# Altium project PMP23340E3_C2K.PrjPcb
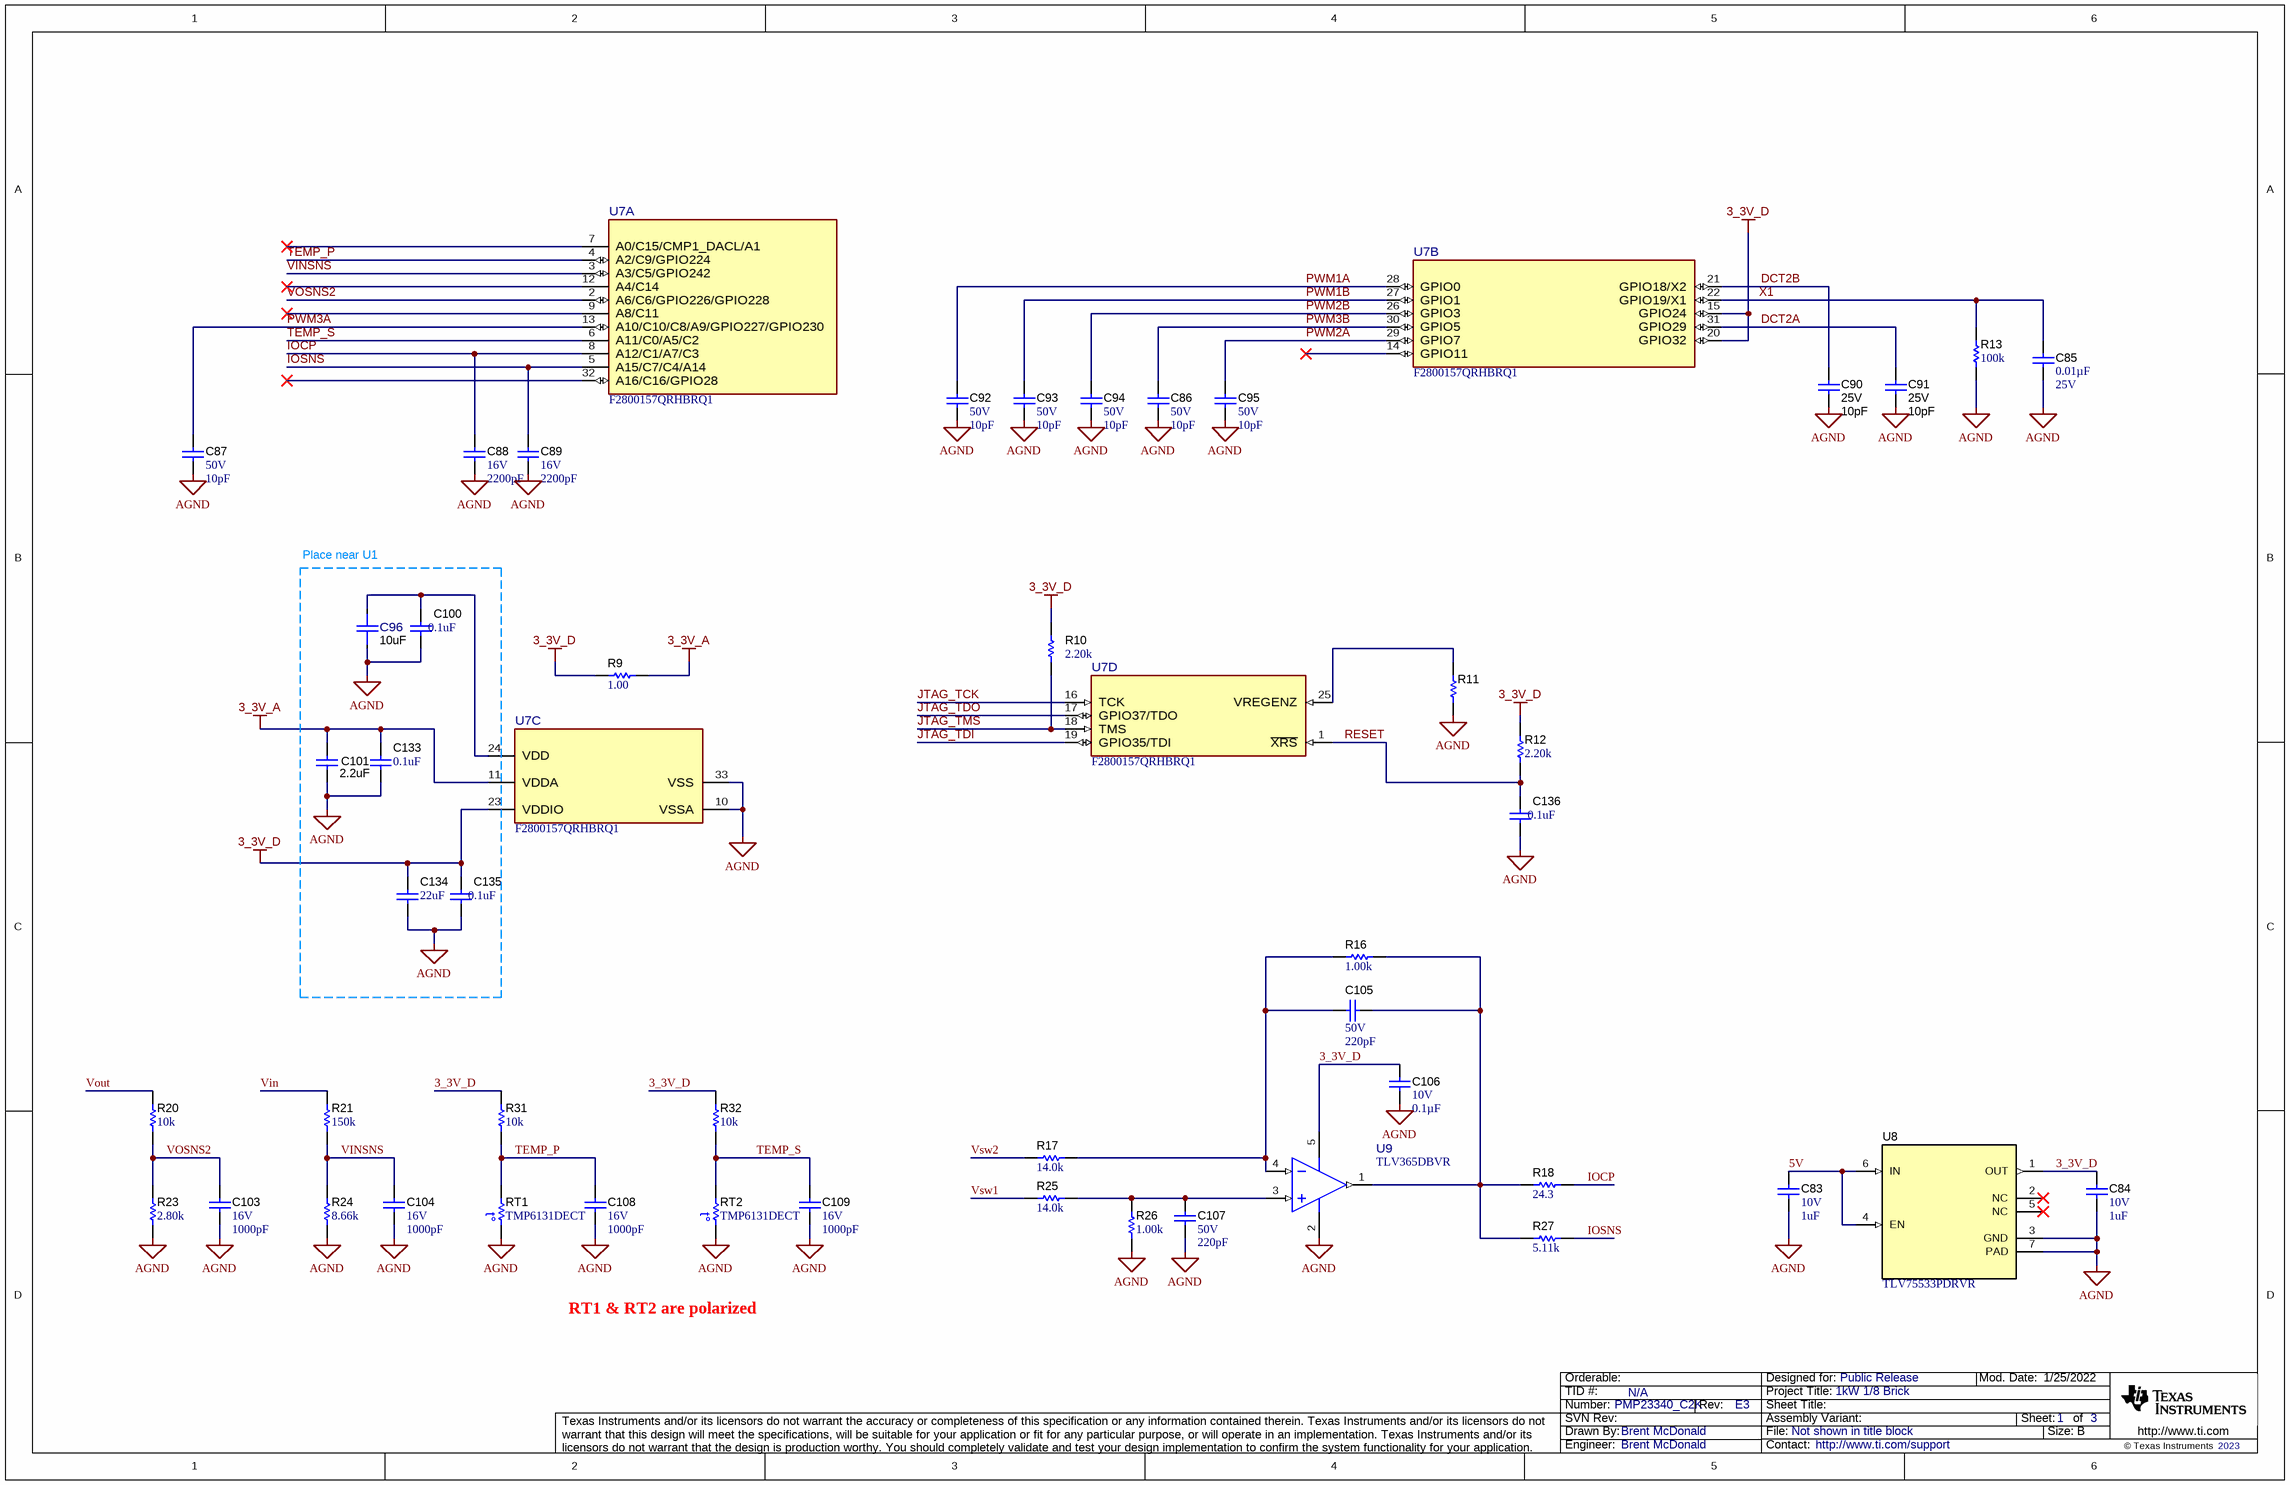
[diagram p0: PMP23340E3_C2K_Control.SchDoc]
CopyrightYear: 2023; DrawnBy: Brent McDonald; PCB_Layout: Brent McDonald; PCB_Rev: E3; PRJ_Customer: Public Release; PRJ_Engineer: Brent McDonald; PRJ_Number: PMP23340_C2K; PRJ_Title: 1kW 1/8 Brick; SCH_Rev: E3; TechSupport: http://www.ti.com/support; TID: N/A
3 sheets, 242 parts. Net scope: global (net labels, ports and power ports of the same name join across sheets).
Board file: PMP23340E3_C2K.PcbDoc
Sheets:
  PMP23340E3_C2K_Control.SchDoc
  PMP23340E3_C2K_Power_Stage.SchDoc
  PMP23340E3_C2K_Hardware.SchDoc

## Sheet PMP23340E3_C2K_Control.SchDoc
size 431 x 279 mm; Date: Not shown in title block; ApprovedBy: Not shown in title block; CheckedBy: Not shown in title block; Author: Not shown in title block; CompanyName: Not shown in title block; Engineer: Not shown in title block; Organization: Not shown in title block; Address1: Not shown in title block; Address2: Not shown in title block; Address3: Not shown in title block; Address4: Not shown in title block; DocumentNumber: 1; Revision: Use project parameter SCH_Rev; SheetNumber: 1; SheetTotal: 3; PageSetup: Record=PageOptions¦CenterHorizontal=True¦CenterVertical=True¦PrintScale=1.00¦XCorrection=1.00¦YCorrection=1.00¦PrintKind=0¦BorderSize=5000000¦LeftOffset=0¦BottomOffset=0¦Orientation=2¦PaperLength=1000¦PaperWidth=1000¦Scale=100¦PaperSource=15¦PrintQuality=600¦MediaType=1¦DitherType=10¦PaperKind=Letter¦PrintScaleMode=1

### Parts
C83  VDC_V: 10V  ValueDisplayed: 1uF  [0201]  (hidden comment: GRM033R61A105ME15D)
C84  VDC_V: 10V  ValueDisplayed: 1uF  [0201]  (hidden comment: GRM033R61A105ME15D)
C85  ValueDisplayed: 0.01µF  VDC_V: 25V  [0201_033]  (hidden comment: GRM033R61E103KA12D)
C86  VDC_V: 50V  ValueDisplayed: 10pF  [0201_033]  (hidden comment: GRM0335C1H100JA01D)
C87  VDC_V: 50V  ValueDisplayed: 10pF  [0201_033]  (hidden comment: GRM0335C1H100JA01D)
C88  VDC_V: 16V  ValueDisplayed: 2200pF  [0201]  (hidden comment: GRM033R71C222KA88D)
C89  VDC_V: 16V  ValueDisplayed: 2200pF  [0201]  (hidden comment: GRM033R71C222KA88D)
C90  VDC_V: 25V  ValueDisplayed: 10pF  [0201]  (hidden comment: GJM0335C1E100JB01D)
C91  VDC_V: 25V  ValueDisplayed: 10pF  [0201]  (hidden comment: GJM0335C1E100JB01D)
C92  VDC_V: 50V  ValueDisplayed: 10pF  [0201_033]  (hidden comment: GRM0335C1H100JA01D)
C93  VDC_V: 50V  ValueDisplayed: 10pF  [0201_033]  (hidden comment: GRM0335C1H100JA01D)
C94  VDC_V: 50V  ValueDisplayed: 10pF  [0201_033]  (hidden comment: GRM0335C1H100JA01D)
C95  VDC_V: 50V  ValueDisplayed: 10pF  [0201_033]  (hidden comment: GRM0335C1H100JA01D)
C96  ValueDisplayed: 10uF  [FP-CC0603KRX5R6BB106_0603-MFG]  (hidden comment: CC0603KRX5R6BB106)
C100  ValueDisplayed: 0.1uF  [0201]  (hidden comment: GRM033Z71C104KE14D)
C101  ValueDisplayed: 2.2uF  [0603]  (hidden comment: GRM188R61A225KE34D)
C103  VDC_V: 16V  ValueDisplayed: 1000pF  [0201]  (hidden comment: GRM033R71C102KA01D)
C104  VDC_V: 16V  ValueDisplayed: 1000pF  [0201]  (hidden comment: GRM033R71C102KA01D)
C105  VDC_V: 50V  ValueDisplayed: 220pF  [0201_033]  (hidden comment: CGA1A2X7R1H221K030BA)
C106  VDC_V: 10V  ValueDisplayed: 0.1µF  [0201_033L]  (hidden comment: ATC530Z104KT10T)
C107  VDC_V: 50V  ValueDisplayed: 220pF  [0201_033]  (hidden comment: CGA1A2X7R1H221K030BA)
C108  VDC_V: 16V  ValueDisplayed: 1000pF  [0201]  (hidden comment: GRM033R71C102KA01D)
C109  VDC_V: 16V  ValueDisplayed: 1000pF  [0201]  (hidden comment: GRM033R71C102KA01D)
C133  ValueDisplayed: 0.1uF  [0201]  (hidden comment: GRM033Z71C104KE14D)
C134  ValueDisplayed: 22uF  [0603]  (hidden comment: GRM187R61A226ME15D)
C135  ValueDisplayed: 0.1uF  [0201]  (hidden comment: GRM033Z71C104KE14D)
C136  ValueDisplayed: 0.1uF  [0201]  (hidden comment: GRM033Z71C104KE14D)
R9  ValueDisplayed: 1.00  [0201]  (hidden comment: RC0201FR-071RL)
R10  ValueDisplayed: 2.20k  [0201]  (hidden comment: CRCW02012K20FKED)
R11  RC0201JR-070RL  [FP-RC0201JR-070RL_0201 (0603 Metric)-IPC_C]  (value not drawn)
R12  ValueDisplayed: 2.20k  [0201]  (hidden comment: CRCW02012K20FKED)
R13  ValueDisplayed: 100k  [0402]  (hidden comment: RG1005P-104-B-T5)
R16  ValueDisplayed: 1.00k  [0201]  (hidden comment: RC0201FS-7D1KL)
R17  ValueDisplayed: 14.0k  [0402]  (hidden comment: RC0402FR-0714KL)
R18  ValueDisplayed: 24.3  [0201]  (hidden comment: RC0201FS-7D24R3L)
R20  ValueDisplayed: 10k  [0201]  (hidden comment: RC0201JR-7D10KL)
R21  ValueDisplayed: 150k  [0402]  (hidden comment: ERJ-2RKF1503X)
R23  ValueDisplayed: 2.80k  [0201]  (hidden comment: RC0201FR-072K8L)
R24  ValueDisplayed: 8.66k  [0201]  (hidden comment: RC0201FR-078K66L)
R25  ValueDisplayed: 14.0k  [0402]  (hidden comment: RC0402FR-0714KL)
R26  ValueDisplayed: 1.00k  [0201]  (hidden comment: RC0201FS-7D1KL)
R27  ValueDisplayed: 5.11k  [0201]  (hidden comment: RC0201FR-075K11L)
R31  ValueDisplayed: 10k  [0201]  (hidden comment: RC0201JS-7D10KL)
R32  ValueDisplayed: 10k  [0201]  (hidden comment: RC0201JS-7D10KL)
RT1  TMP6131DECT  [DEC0002A]
RT2  TMP6131DECT  [DEC0002A]
U7  F2800157QRHBRQ1  [RHB0032E-MFG]  (parts A,B,C,D of 4)
U8  TLV75533PDRVR  [DRV0006A]
U9  TLV365DBVR  [DBV0005A-MFG]

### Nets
3_3V_A: C101.1 C133.1 R9.2 U7.11(VDDA)
3_3V_D: C84.1 C106.1 C134.1 C135.1 R9.1 R10.2 R12.2 R31.2 R32.2 U7.15(GPIO24) U7.20(GPIO32) U7.23(VDDIO) U8.1(OUT) U9.5(V+)
AGND: C83.2 C84.2 C85.2 C86.2 C87.2 C88.1 C89.1 C90.2 C91.2 C92.2 C93.2 C94.2 C95.2 C96.1 C100.2 C101.2 C103.1 C104.1 C106.2 C107.1 C108.1 C109.1 C133.2 C134.2 C135.2 C136.2 R11.1 R13.2 R23.1 R24.1 R26.1 RT1.2 RT2.2 U7.10(VSSA) U7.33(VSS) U8.3(GND) U8.7(PAD) U9.2(V-)
5V: C83.1 U8.4(EN) U8.6(IN)
DCT2A: C91.1 U7.31(GPIO29)
DCT2B: C90.1 U7.21(GPIO18/X2)
IOCP: C88.2 R18.2 U7.8(A12/C1/A7/C3)
IOSNS: C89.2 R27.2 U7.5(A15/C7/C4/A14)
JTAG_TCK: U7.16(TCK)
JTAG_TDI: U7.19(GPIO35/TDI)
JTAG_TDO: U7.17(GPIO37/TDO)
JTAG_TMS: R10.1 U7.18(TMS)
PWM1A: C92.1 U7.28(GPIO0)
PWM1B: C93.1 U7.27(GPIO1)
PWM2A: C95.1 U7.29(GPIO7)
PWM2B: C94.1 U7.26(GPIO3)
PWM3A: C87.1 U7.13(A10/C10/C8/A9/GPIO227/GPIO230)
PWM3B: C86.1 U7.30(GPIO5)
RESET: C136.1 R12.1 U7.1(~{XRS})
TEMP_P: C108.2 R31.1 RT1.1 U7.4(A2/C9/GPIO224)
TEMP_S: C109.2 R32.1 RT2.1 U7.6(A11/C0/A5/C2)
Vin: R21.2
VINSNS: C104.2 R21.1 R24.2 U7.3(A3/C5/GPIO242)
VOSNS2: C103.2 R20.1 R23.2 U7.2(A6/C6/GPIO226/GPIO228)
Vout: R20.2
Vsw1: R25.1
Vsw2: R17.1
X1: C85.1 R13.1 U7.22(GPIO19/X1)
NetC96_2: C96.2 C100.1 U7.24(VDD)
NetC105_1: C105.1 R16.1 R18.1 R27.1 U9.1(VOUT)
NetC105_2: C105.2 R16.2 R17.2 U9.4(-IN)
NetC107_2: C107.2 R25.2 R26.2 U9.3(+IN)
NetR11_2: R11.2 U7.25(VREGENZ)

Not connected (* = marked no-connect by the designer): U7 7(A0/C15/CMP1_DACL/A1)* 9(A8/C11)* 12(A4/C14)* 14(GPIO11)* 32(A16/C16/GPIO28)*; U8 2(NC)* 5(NC)*

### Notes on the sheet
- Place near U1
- RT1 & RT2 are polarized

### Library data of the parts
C83 C84 = CMP-0064909-1: CAP, CERM, 1 uF, 10 V,+/- 20%, X5R, 0201; Manufacturer: MuRata; TaMin_C: -55°C; Polarized: N; SizeAreaWB_mm2: 2.08; Value1: Unknown; U/M: EA; Value: 1uF; TaMax_C: 85°C; SizeZ_mm: 0.26; SizeX_mm: 0.6; SizeY_mm: 0.3; SizeArea_mm2: 0.18; Cap_F: 1µF; AEC Category: Q200
C85 = CMP-0086060-1: CAP, CERM, 0.01 µF, 25 V,+/- 10%, X5R, 0201; Manufacturer: MuRata; SizeY_mm: 0.3; SizeZ_mm: 0.33; SizeAreaWB_mm2: 2.08; U/M: EA; AEC Category: Q200; SizeX_mm: 0.6; TaMin_C: -55°C; Polarized: N; TaMax_C: 85°C; Value: 0.01uF; Cap_F: 10nF; SizeArea_mm2: 0.18; Cap_Case: 0201
C86 C87 C92-C95 = CMP-0086057-1: CAP, CERM, 10 pF, 50 V,+/- 5%, C0G/NP0, 0201; Manufacturer: MuRata; SizeArea_mm2: 0.18; AEC Category: Q200; SizeX_mm: 0.6; SizeZ_mm: 0.33; Value: 10pF; TaMin_C: -55°C; SizeAreaWB_mm2: 2.08; U/M: EA; AEC Qualified: N; Cap_Case: 0201; SizeY_mm: 0.3; TaMax_C: 125°C
C88 C89 = CMP-0009752-1: CAP, CERM, 2200 pF, 16 V, +/- 10%, X7R, 0201; Manufacturer: MuRata; TaMin_C: -55°C; Polarized: N; SizeAreaWB_mm2: 2.08; Value1: Unknown; U/M: EA; Value: 2200pF; TaMax_C: 125°C; SizeZ_mm: 0.26; SizeX_mm: 0.6; SizeY_mm: 0.3; SizeArea_mm2: 0.18; Cap_F: 2.2nF; AEC Category: Q200
C90 C91 = CMP-0009661-3: CAP, CERM, 10 pF, 25 V, +/- 5%, C0G/NP0, 0201; Manufacturer: MuRata; TaMin_C: -55°C; Polarized: N; SizeAreaWB_mm2: 2.08; Value1: Unknown; U/M: EA; Value: 10pF; TaMax_C: 125°C; SizeZ_mm: 0.26; SizeX_mm: 0.6; SizeY_mm: 0.3; SizeArea_mm2: 0.18; AEC Category: Q200
C96 = CMP-0092309-1: Cap Ceramic 10uF 10V X5R 10% SMD 0603 85C Paper T/R; Manufacturer: YAGEO; Cap_F: 10µF; TempCo: 15%; Category 7542B8484461Ae85: Passive Components; Category 4C11811B7D3097D6: Single Components; SizeZ_mm: 1mm; Category F8883582C9A8234F: Capacitors; AEC Qualified: No; Value: 10µF; Category 85Ce48C4B2B95E09: Uncategorized
C100 C133 C135 C136 = CMP-0064970-1: CAP, CERM, 0.1 uF, 16 V,+/- 10%, X7R, 0201; Manufacturer: MuRata; AEC Qualified: N; Value: 0.1uF; SizeZ_mm: 0.26; VDC_V: 16V; Cap_F: 100nF; TaMin_C: -55°C; SizeAreaWB_mm2: 2.08; Value1: Unknown; U/M: EA; TaMax_C: 125°C; SizeX_mm: 0.6; SizeY_mm: 0.3; SizeArea_mm2: 0.18; AEC Category: Q200
C101 = CMP-0007323-5: CAP, CERM, 2.2 uF, 10 V, +/- 10%, X5R, 0603; Manufacturer: MuRata; Polarized: N; Value: 2.2uF; U/M: EA; Cap_F: 2.2µF; Value1: Unknown; VDC_V: 10V; TaMin_C: -55°C; TaMax_C: 85°C; SizeArea_mm2: 1.28; SizeAreaWB_mm2: 4.68; SizeX_mm: 1.6; SizeY_mm: 0.8; SizeZ_mm: 1; AEC Category: Q200
C103 C104 C108 C109 = CMP-0009745-1: CAP, CERM, 1000 pF, 16 V, +/- 10%, X7R, 0201; Manufacturer: MuRata; TaMin_C: -55°C; Polarized: N; SizeAreaWB_mm2: 2.08; Value1: Unknown; U/M: EA; Value: 1000pF; TaMax_C: 125°C; SizeZ_mm: 0.26; SizeX_mm: 0.6; SizeY_mm: 0.3; SizeArea_mm2: 0.18; Cap_F: 1nF; AEC Category: Q200
C105 C107 = CMP-0009652-3: CAP, CERM, 220 pF, 50 V, +/- 10%, X7R, AEC-Q200 Grade 1, 0201; Manufacturer: TDK; TaMin_C: -55°C; ESR_ohm: 11.6275; Polarized: N; SizeAreaWB_mm2: 2.08; Value1: 11.6275 ohm; U/M: EA; Value: 220pF; TaMax_C: 125°C; SizeZ_mm: 0.33; SizeX_mm: 0.6; SizeY_mm: 0.3; SizeArea_mm2: 0.18; AEC Qualified: Y; IRMS_A: 200.785mA; AEC Grade: 1; AEC Category: Q200
C106 = CMP-0076713-1: CAP, CERM, 0.1 µF, 10 V,+/- 10%, X5R, 0201; Manufacturer: AT Ceramics; Cap_F: 100nF; SizeAreaWB_mm2: 2.08; SizeArea_mm2: 0.18; AEC Qualified: N; AEC Category: Q200; Value: 0.1uF; TaMax_C: 85°C; SizeZ_mm: 0.33; TaMin_C: -55°C; SizeY_mm: 0.3; U/M: EA; SizeX_mm: 0.6; Cap_Case: 0201
C134 = CMP-0007158-5: CAP, CERM, 22 uF, 10 V, +/- 20%, X5R, 0603; Manufacturer: MuRata; Cap_F: 22µF; SizeZ_mm: 1; VDC_V: 10V; AEC Qualified: N; Value: 22uF; TaMin_C: -55°C; SizeAreaWB_mm2: 4.68; Value1: Unknown; U/M: EA; TaMax_C: 85°C; SizeX_mm: 1.6; SizeY_mm: 0.8; SizeArea_mm2: 1.28; AEC Category: Q200
R9 = CMP-0027472-1: RES, 1.00, 1%, 0.05 W, 0201; Manufacturer: Yageo America; Power_W: 50mW; TempCo: 350 ppm/C; Value_Code: 1R00; U/M: EA; Value: 1.00; EIA_Code: E96; Res_ohm: 1; SizeX_mm: 0.6; SizeY_mm: 0.3; SizeZ_mm: 0.26; Value2: 0.05W; SizeArea_mm2: 0.18; AEC Qualified: N; VDC_V: 25V; AEC Category: Q200
R10 R12 = CMP-0027272-3: RES, 2.20 k, 1%, 0.05 W, 0201; Manufacturer: Vishay-Dale; Value: 2.20k; Res_ohm: 2.2k; Value_Code: 2k20; Power_W: 50mW; Value2: 0.05W; VDC_V: 30V; TempCo: 100 ppm/C; AEC Category: Q200; AEC Qualified: N; SizeArea_mm2: 0.18; SizeX_mm: 0.6; SizeY_mm: 0.3; SizeZ_mm: 0.26
R11 = CMP-0086442-2: RES SMD 0 OHM JUMPER 1/20W 0201; Manufacturer: Yageo; Res_ohm: 0; Tolerance_%: 5%; Power_W: 50mW; VDC_V: 25V; TempCo: 200ppm/°C; AEC Qualified: No; SizeZ_mm: 0.26mm
R13 = CMP-0026815-1: RES, 100 k, 0.1%, 0.063 W, 0402; Manufacturer: Susumu Co Ltd; Power_W: 63mW; TempCo: 25 ppm/C; U/M: EA; Value: 100k; EIA_Code: E192; SizeX_mm: 1; SizeY_mm: 0.5; SizeZ_mm: 0.6; Value2: 0.063W; AEC Category: Q200
R16 R26 = CMP-0028084-1: RES, 1.00 k, 1%, 0.05 W, 0201; Manufacturer: Yageo America; Power_W: 50mW; TempCo: 200 ppm/C; Value_Code: 1k00; U/M: EA; Value: 1.00k; EIA_Code: E96; Res_ohm: 1k; SizeX_mm: 0.6; SizeY_mm: 0.3; SizeZ_mm: 0.26; Value2: 0.05W; SizeArea_mm2: 0.18; AEC Qualified: N; VDC_V: 25V; AEC Category: Q200
R17 R25 = CMP-0860046-1: RES, 14.0 k, 1%, 0.0625 W, 0402; Manufacturer: Yageo; Power_W: 62.5mW; TempCo: 100 ppm/C; Value_Code: 14k0; Value: 14.0k; EIA_Code: E96; Res_ohm: 14k; SizeX_mm: 1; SizeY_mm: 0.5; SizeZ_mm: 0.6; AEC Qualified: N; VDC_V: 50V; AEC Category: Q200; SizeAreaWB_mm2: 3
R18 = CMP-0028092-1: RES, 24.3, 1%, 0.05 W, 0201; Manufacturer: Yageo America; Power_W: 50mW; TempCo: 200 ppm/C; Value_Code: 24R3; U/M: EA; Value: 24.3; EIA_Code: E96; SizeX_mm: 0.6; SizeY_mm: 0.3; SizeZ_mm: 0.26; Value2: 0.05W; SizeArea_mm2: 0.18; AEC Qualified: N; VDC_V: 25V; AEC Category: Q200
R20 = CMP-0027186-1: RES, 10 k, 5%, 0.05 W, 0201; Manufacturer: Yageo America; Power_W: 50mW; TempCo: 200 ppm/C; Value_Code: 10k0; U/M: EA; Value: 10k; EIA_Code: E24; SizeX_mm: 0.6; SizeY_mm: 0.3; SizeZ_mm: 0.26; Value2: 0.05W; SizeArea_mm2: 0.18; AEC Qualified: N; VDC_V: 25V; AEC Category: Q200
R21 = CMP-0026669-1: RES, 150 k, 1%, 0.1 W, AEC-Q200 Grade 0, 0402; Manufacturer: Panasonic; Power_W: 100mW; TempCo: 100 ppm/C; U/M: EA; Value: 150k; EIA_Code: E96; SizeX_mm: 1; SizeY_mm: 0.5; SizeZ_mm: 0.6; Value2: 0.1W; AEC Qualified: Y; VDC_V: 50V; AEC Grade: 0; AEC Category: Q200
R23 = CMP-0027570-1: RES, 2.80 k, 1%, 0.05 W, 0201; Manufacturer: Yageo America; Power_W: 50mW; TempCo: 200 ppm/C; Value_Code: 2k80; U/M: EA; Value: 2.80k; EIA_Code: E96; Res_ohm: 2.8k; SizeX_mm: 0.6; SizeY_mm: 0.3; SizeZ_mm: 0.26; Value2: 0.05W; SizeArea_mm2: 0.18; AEC Qualified: N; VDC_V: 25V; AEC Category: Q200
R24 = CMP-0027911-1: RES, 8.66 k, 1%, 0.05 W, 0201; Manufacturer: Yageo America; Power_W: 50mW; TempCo: 200 ppm/C; Value_Code: 8k66; U/M: EA; Value: 8.66k; EIA_Code: E96; SizeX_mm: 0.6; SizeY_mm: 0.3; SizeZ_mm: 0.26; Value2: 0.05W; SizeArea_mm2: 0.18; AEC Qualified: N; VDC_V: 25V; AEC Category: Q200
R27 = CMP-0027788-1: RES, 5.11 k, 1%, 0.05 W, 0201; Manufacturer: Yageo America; Power_W: 50mW; TempCo: 200 ppm/C; Value_Code: 5k11; U/M: EA; Value: 5.11k; EIA_Code: E96; SizeX_mm: 0.6; SizeY_mm: 0.3; SizeZ_mm: 0.26; Value2: 0.05W; SizeArea_mm2: 0.18; AEC Qualified: N; VDC_V: 25V; AEC Category: Q200
R31 R32 = CMP-0027260-1: RES, 10 k, 5%, 0.05 W, 0201; Manufacturer: Yageo America; Power_W: 50mW; TempCo: 200 ppm/C; Value_Code: 10k0; U/M: EA; Value: 10k; EIA_Code: E24; SizeX_mm: 0.6; SizeY_mm: 0.3; SizeZ_mm: 0.26; Value2: 0.05W; SizeArea_mm2: 0.18; AEC Qualified: N; VDC_V: 25V; AEC Category: Q200
RT1 RT2 = CMP-0084565-1: Thermistor, DEC0002A (X1SON-2); Alternate Manufacturer: Texas Instruments; Alternate PartNumber: TMP6131DECR; SizeZ_mm: 0.5; CompType: IC; AEC Category: Q200; SizeArea_mm2: 0.6; AEC Qualified: N; SizeX_mm: 1; SizeAreaWB_mm2: 3.2
U7 = CMP-0097759-1: Real-Time Microcontrollers VQFN32 TMS320C28x 32bit 120MHz; Manufacturer: Texas Instruments; AEC Grade: Grade 1; Max Supply Voltage: 3.63V; Min Supply Voltage: 1.14V; Number Of A/D Converters: 2; Number Of I/Os: 18; Number Of Timers/Counters: 3; SizeZ_mm: 1mm; Standoff Height: 0mm; Memory Type: FLASH; Ram Size: 36KBytes; TJmax_C: +140°C; Data Bus Width: 32bits; Interface: I2C,SPI,UART,CAN,LIN,SCI,Other; Memory Size: 256KBytes; Number Of Adc Channels: 11; Number Of Spi Channels: 1; AEC Qualified: Yes; Number Of Uart Channels: 4; Number Of Pwm Channels: 14; TaMax_C: +125°C; TaMin_C: -40°C
U8 = CMP-0013427-7: 500mA LDO, DRV0006A (WSON-6); Manufacturer: Texas Instruments; SizeX_mm: 2; CompType: IC; SizeZ_mm: 0.8; SizeArea_mm2: 4; SizeAreaWB_mm2: 9; U/M: EA
U9 = CMP-0032028-2: CMOS Amplifier 1 Circuit Rail-to-Rail SOT-23-5; Manufacturer: Texas Instruments; Number Of Channels: 1; Gain Bandwidth: 50MHz; SizeZ_mm: 1.45mm; AEC Qualified: No; Input Bias Current: 0.000005uA; Input Offset Voltage: 0.4mV; Max Supply Voltage: 5.5V; Min Supply Voltage: 2.2V; Nominal Supply Current: 4.6mA; Output Current Per Channel: 85mA; Response Time: 0.2us; Standoff Height: 0mm; TaMax_C: +125°C; TaMin_C: -40°C; TJmax_C: +150°C; Voltage Gain: 120dB; AEC Category: Q200; CompType: IC

## Sheet PMP23340E3_C2K_Power_Stage.SchDoc
size 431 x 279 mm; Date: Not shown in title block; ApprovedBy: Not shown in title block; CheckedBy: Not shown in title block; Author: Not shown in title block; CompanyName: Not shown in title block; Engineer: Not shown in title block; Organization: Not shown in title block; Address1: Not shown in title block; Address2: Not shown in title block; Address3: Not shown in title block; Address4: Not shown in title block; DocumentNumber: 2; Revision: Use project parameter SCH_Rev; SheetNumber: 2; SheetTotal: 3; PageSetup: Record=PageOptions¦CenterHorizontal=True¦CenterVertical=True¦PrintScale=1.00¦XCorrection=1.00¦YCorrection=1.00¦PrintKind=0¦BorderSize=5000000¦LeftOffset=0¦BottomOffset=0¦Orientation=2¦PaperLength=1000¦PaperWidth=1000¦Scale=100¦PaperSource=15¦PrintQuality=600¦MediaType=1¦DitherType=10¦PaperKind=Letter¦PrintScaleMode=1
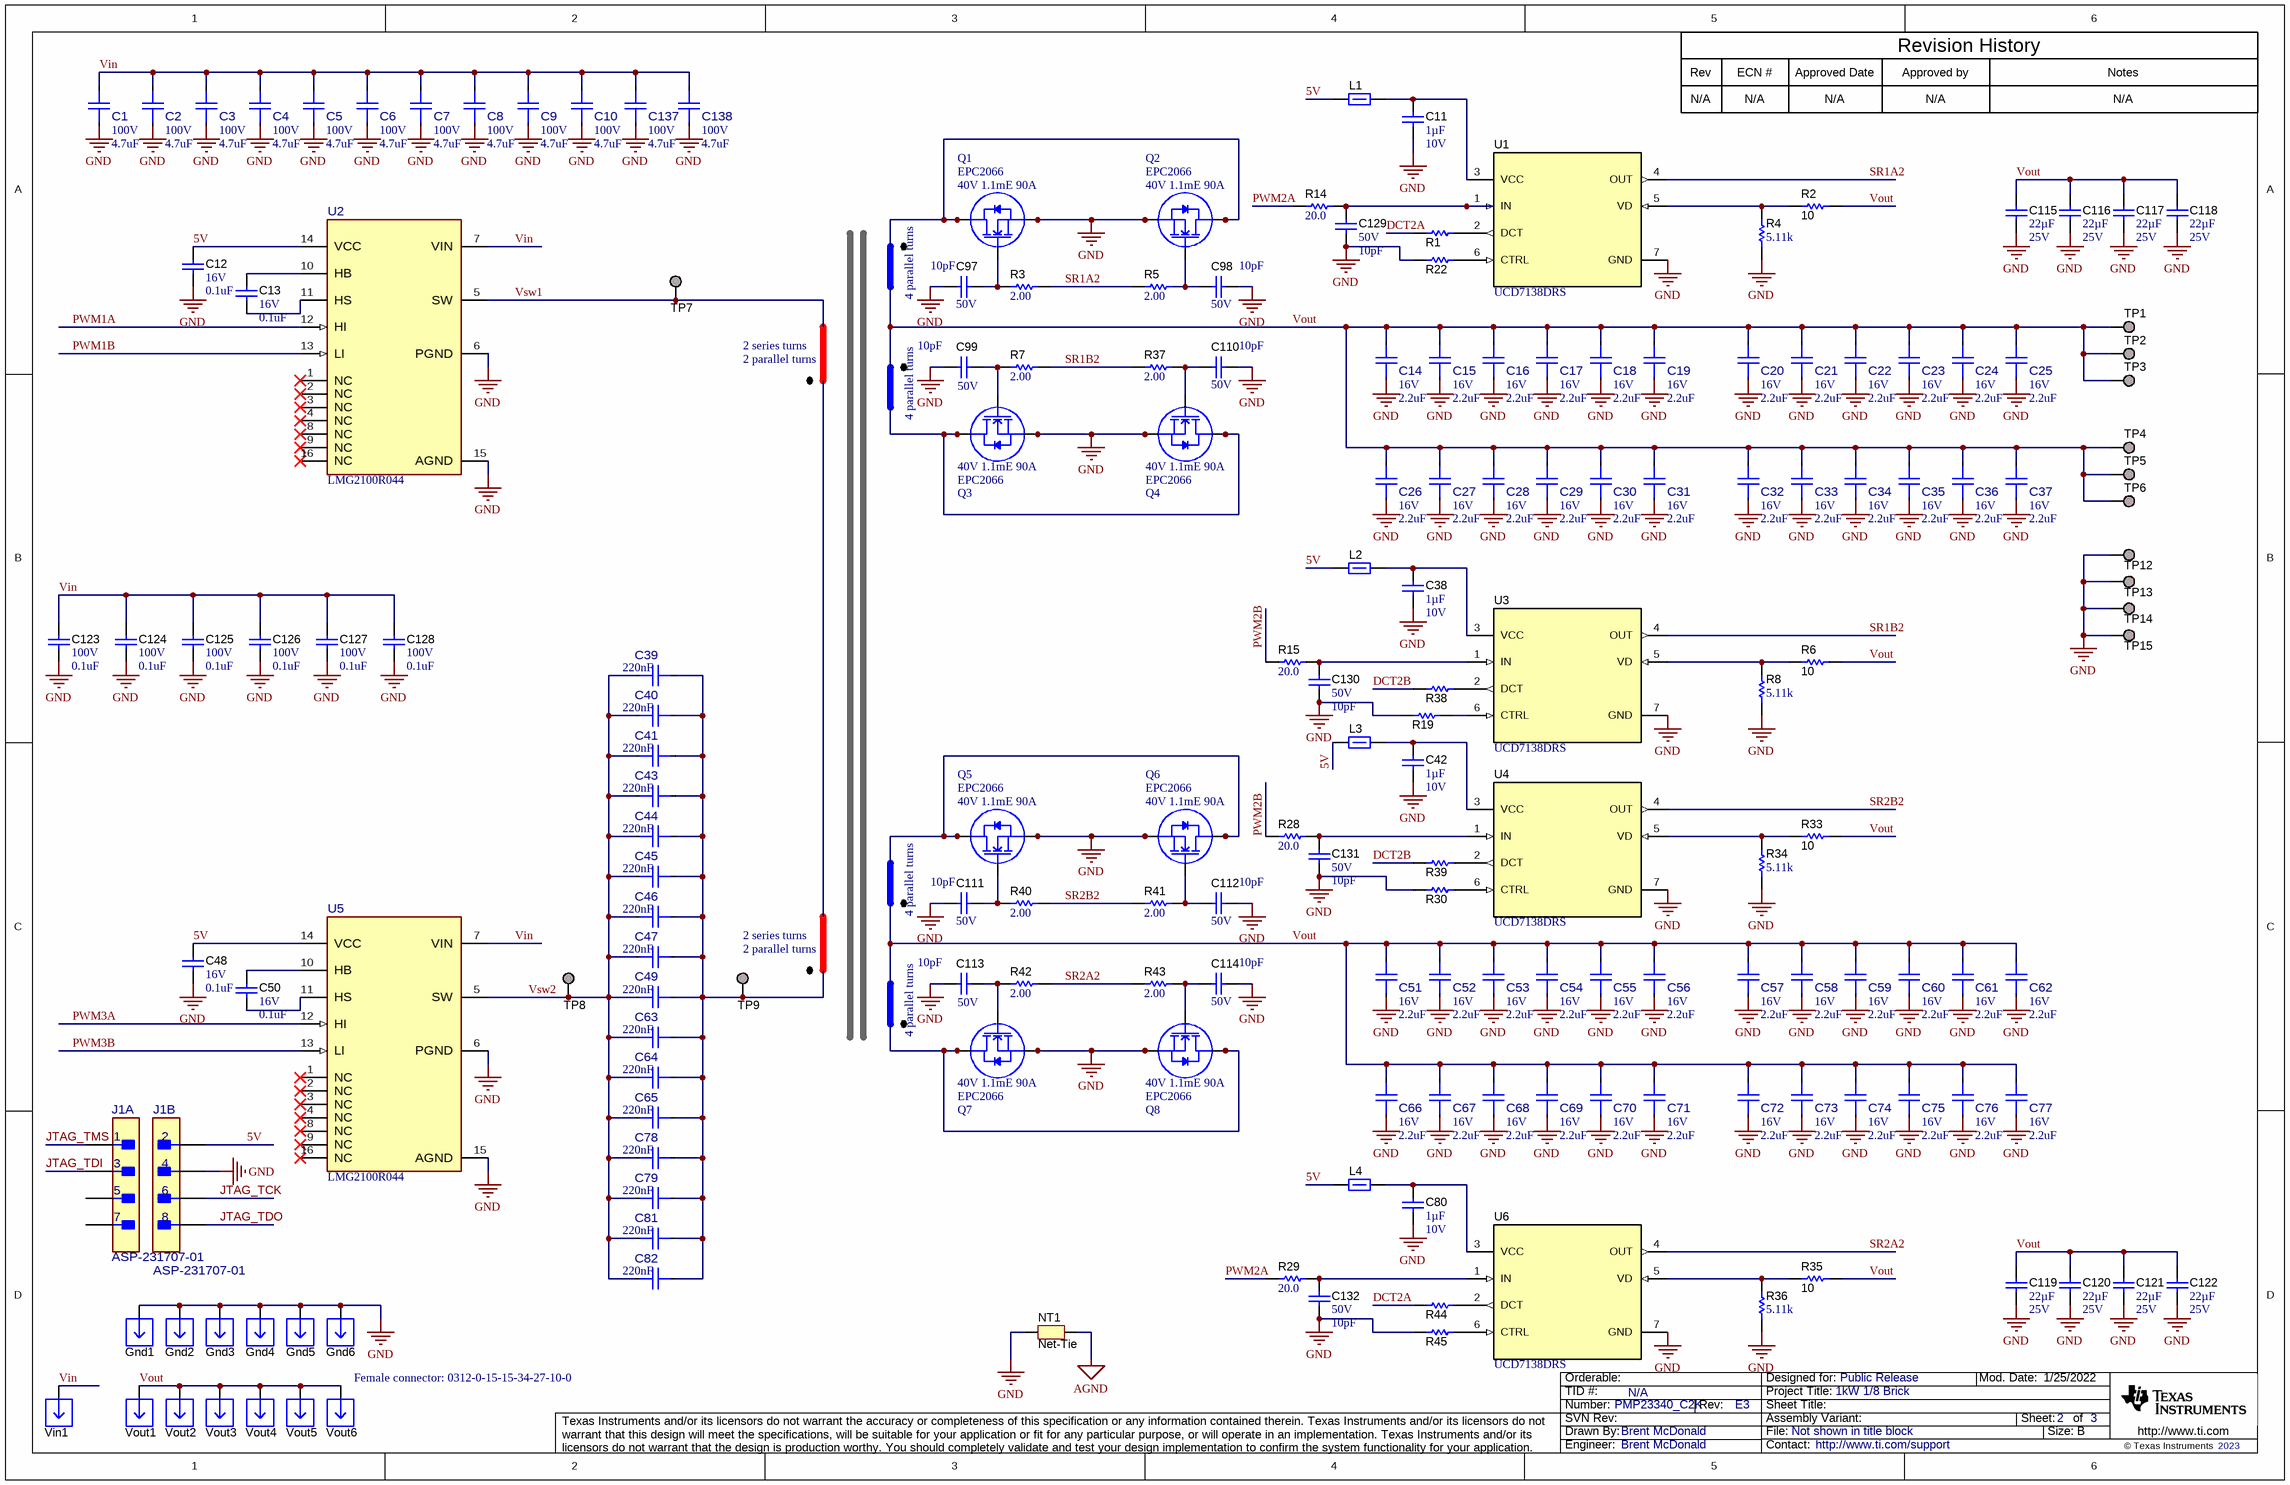
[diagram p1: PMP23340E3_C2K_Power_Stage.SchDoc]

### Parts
C1  VDC_V: 100V  ValueDisplayed: 4.7uF  [FP-C2012X5R2A475K125AC_0805-MFG]  (hidden comment: C2012X5R2A475K125AC)
C2  VDC_V: 100V  ValueDisplayed: 4.7uF  [FP-C2012X5R2A475K125AC_0805-MFG]  (hidden comment: C2012X5R2A475K125AC)
C3  VDC_V: 100V  ValueDisplayed: 4.7uF  [FP-C2012X5R2A475K125AC_0805-MFG]  (hidden comment: C2012X5R2A475K125AC)
C4  VDC_V: 100V  ValueDisplayed: 4.7uF  [FP-C2012X5R2A475K125AC_0805-MFG]  (hidden comment: C2012X5R2A475K125AC)
C5  VDC_V: 100V  ValueDisplayed: 4.7uF  [FP-C2012X5R2A475K125AC_0805-MFG]  (hidden comment: C2012X5R2A475K125AC)
C6  VDC_V: 100V  ValueDisplayed: 4.7uF  [FP-C2012X5R2A475K125AC_0805-MFG]  (hidden comment: C2012X5R2A475K125AC)
C7  VDC_V: 100V  ValueDisplayed: 4.7uF  [FP-C2012X5R2A475K125AC_0805-MFG]  (hidden comment: C2012X5R2A475K125AC)
C8  VDC_V: 100V  ValueDisplayed: 4.7uF  [FP-C2012X5R2A475K125AC_0805-MFG]  (hidden comment: C2012X5R2A475K125AC)
C9  VDC_V: 100V  ValueDisplayed: 4.7uF  [FP-C2012X5R2A475K125AC_0805-MFG]  (hidden comment: C2012X5R2A475K125AC)
C10  VDC_V: 100V  ValueDisplayed: 4.7uF  [FP-C2012X5R2A475K125AC_0805-MFG]  (hidden comment: C2012X5R2A475K125AC)
C11  Cap_F: 1µF  VDC_V: 10V  [0201]  (hidden comment: GRM033R61A105ME15D)
C12  VDC_V: 16V  ValueDisplayed: 0.1uF  [0402_065]  (hidden comment: 160R07X104KV4T)
C13  VDC_V: 16V  ValueDisplayed: 0.1uF  [0402_065]  (hidden comment: 160R07X104KV4T)
C14  VDC_V: 16V  ValueDisplayed: 2.2uF  [FP-GRM155C81C225ME15D_0402-MFG]  (hidden comment: GRM155C81C225ME15D)
C15  VDC_V: 16V  ValueDisplayed: 2.2uF  [FP-GRM155C81C225ME15D_0402-MFG]  (hidden comment: GRM155C81C225ME15D)
C16  VDC_V: 16V  ValueDisplayed: 2.2uF  [FP-GRM155C81C225ME15D_0402-MFG]  (hidden comment: GRM155C81C225ME15D)
C17  VDC_V: 16V  ValueDisplayed: 2.2uF  [FP-GRM155C81C225ME15D_0402-MFG]  (hidden comment: GRM155C81C225ME15D)
C18  VDC_V: 16V  ValueDisplayed: 2.2uF  [FP-GRM155C81C225ME15D_0402-MFG]  (hidden comment: GRM155C81C225ME15D)
C19  VDC_V: 16V  ValueDisplayed: 2.2uF  [FP-GRM155C81C225ME15D_0402-MFG]  (hidden comment: GRM155C81C225ME15D)
C20  VDC_V: 16V  ValueDisplayed: 2.2uF  [FP-GRM155C81C225ME15D_0402-MFG]  (hidden comment: GRM155C81C225ME15D)
C21  VDC_V: 16V  ValueDisplayed: 2.2uF  [FP-GRM155C81C225ME15D_0402-MFG]  (hidden comment: GRM155C81C225ME15D)
C22  VDC_V: 16V  ValueDisplayed: 2.2uF  [FP-GRM155C81C225ME15D_0402-MFG]  (hidden comment: GRM155C81C225ME15D)
C23  VDC_V: 16V  ValueDisplayed: 2.2uF  [FP-GRM155C81C225ME15D_0402-MFG]  (hidden comment: GRM155C81C225ME15D)
C24  VDC_V: 16V  ValueDisplayed: 2.2uF  [FP-GRM155C81C225ME15D_0402-MFG]  (hidden comment: GRM155C81C225ME15D)
C25  VDC_V: 16V  ValueDisplayed: 2.2uF  [FP-GRM155C81C225ME15D_0402-MFG]  (hidden comment: GRM155C81C225ME15D)
C26  VDC_V: 16V  ValueDisplayed: 2.2uF  [FP-GRM155C81C225ME15D_0402-MFG]  (hidden comment: GRM155C81C225ME15D)
C27  VDC_V: 16V  ValueDisplayed: 2.2uF  [FP-GRM155C81C225ME15D_0402-MFG]  (hidden comment: GRM155C81C225ME15D)
C28  VDC_V: 16V  ValueDisplayed: 2.2uF  [FP-GRM155C81C225ME15D_0402-MFG]  (hidden comment: GRM155C81C225ME15D)
C29  VDC_V: 16V  ValueDisplayed: 2.2uF  [FP-GRM155C81C225ME15D_0402-MFG]  (hidden comment: GRM155C81C225ME15D)
C30  VDC_V: 16V  ValueDisplayed: 2.2uF  [FP-GRM155C81C225ME15D_0402-MFG]  (hidden comment: GRM155C81C225ME15D)
C31  VDC_V: 16V  ValueDisplayed: 2.2uF  [FP-GRM155C81C225ME15D_0402-MFG]  (hidden comment: GRM155C81C225ME15D)
C32  VDC_V: 16V  ValueDisplayed: 2.2uF  [FP-GRM155C81C225ME15D_0402-MFG]  (hidden comment: GRM155C81C225ME15D)
C33  VDC_V: 16V  ValueDisplayed: 2.2uF  [FP-GRM155C81C225ME15D_0402-MFG]  (hidden comment: GRM155C81C225ME15D)
C34  VDC_V: 16V  ValueDisplayed: 2.2uF  [FP-GRM155C81C225ME15D_0402-MFG]  (hidden comment: GRM155C81C225ME15D)
C35  VDC_V: 16V  ValueDisplayed: 2.2uF  [FP-GRM155C81C225ME15D_0402-MFG]  (hidden comment: GRM155C81C225ME15D)
C36  VDC_V: 16V  ValueDisplayed: 2.2uF  [FP-GRM155C81C225ME15D_0402-MFG]  (hidden comment: GRM155C81C225ME15D)
C37  VDC_V: 16V  ValueDisplayed: 2.2uF  [FP-GRM155C81C225ME15D_0402-MFG]  (hidden comment: GRM155C81C225ME15D)
C38  Cap_F: 1µF  VDC_V: 10V  [0201]  (hidden comment: GRM033R61A105ME15D)
C39  value 220nF  [FP-C1206C224K3JAC7800_1206-MFG]  (hidden comment: C1206C224K3JAC7800)
C40  value 220nF  [FP-C1206C224K3JAC7800_1206-MFG]  (hidden comment: C1206C224K3JAC7800)
C41  value 220nF  [FP-C1206C224K3JAC7800_1206-MFG]  (hidden comment: C1206C224K3JAC7800)
C42  Cap_F: 1µF  VDC_V: 10V  [0201]  (hidden comment: GRM033R61A105ME15D)
C43  value 220nF  [FP-C1206C224K3JAC7800_1206-MFG]  (hidden comment: C1206C224K3JAC7800)
C44  value 220nF  [FP-C1206C224K3JAC7800_1206-MFG]  (hidden comment: C1206C224K3JAC7800)
C45  value 220nF  [FP-C1206C224K3JAC7800_1206-MFG]  (hidden comment: C1206C224K3JAC7800)
C46  value 220nF  [FP-C1206C224K3JAC7800_1206-MFG]  (hidden comment: C1206C224K3JAC7800)
C47  value 220nF  [FP-C1206C224K3JAC7800_1206-MFG]  (hidden comment: C1206C224K3JAC7800)
C48  VDC_V: 16V  ValueDisplayed: 0.1uF  [0402_065]  (hidden comment: 160R07X104KV4T)
C49  value 220nF  [FP-C1206C224K3JAC7800_1206-MFG]  (hidden comment: C1206C224K3JAC7800)
C50  VDC_V: 16V  ValueDisplayed: 0.1uF  [0402_065]  (hidden comment: 160R07X104KV4T)
C51  VDC_V: 16V  ValueDisplayed: 2.2uF  [FP-GRM155C81C225ME15D_0402-MFG]  (hidden comment: GRM155C81C225ME15D)
C52  VDC_V: 16V  ValueDisplayed: 2.2uF  [FP-GRM155C81C225ME15D_0402-MFG]  (hidden comment: GRM155C81C225ME15D)
C53  VDC_V: 16V  ValueDisplayed: 2.2uF  [FP-GRM155C81C225ME15D_0402-MFG]  (hidden comment: GRM155C81C225ME15D)
C54  VDC_V: 16V  ValueDisplayed: 2.2uF  [FP-GRM155C81C225ME15D_0402-MFG]  (hidden comment: GRM155C81C225ME15D)
C55  VDC_V: 16V  ValueDisplayed: 2.2uF  [FP-GRM155C81C225ME15D_0402-MFG]  (hidden comment: GRM155C81C225ME15D)
C56  VDC_V: 16V  ValueDisplayed: 2.2uF  [FP-GRM155C81C225ME15D_0402-MFG]  (hidden comment: GRM155C81C225ME15D)
C57  VDC_V: 16V  ValueDisplayed: 2.2uF  [FP-GRM155C81C225ME15D_0402-MFG]  (hidden comment: GRM155C81C225ME15D)
C58  VDC_V: 16V  ValueDisplayed: 2.2uF  [FP-GRM155C81C225ME15D_0402-MFG]  (hidden comment: GRM155C81C225ME15D)
C59  VDC_V: 16V  ValueDisplayed: 2.2uF  [FP-GRM155C81C225ME15D_0402-MFG]  (hidden comment: GRM155C81C225ME15D)
C60  VDC_V: 16V  ValueDisplayed: 2.2uF  [FP-GRM155C81C225ME15D_0402-MFG]  (hidden comment: GRM155C81C225ME15D)
C61  VDC_V: 16V  ValueDisplayed: 2.2uF  [FP-GRM155C81C225ME15D_0402-MFG]  (hidden comment: GRM155C81C225ME15D)
C62  VDC_V: 16V  ValueDisplayed: 2.2uF  [FP-GRM155C81C225ME15D_0402-MFG]  (hidden comment: GRM155C81C225ME15D)
C63  value 220nF  [FP-C1206C224K3JAC7800_1206-MFG]  (hidden comment: C1206C224K3JAC7800)
C64  value 220nF  [FP-C1206C224K3JAC7800_1206-MFG]  (hidden comment: C1206C224K3JAC7800)
C65  value 220nF  [FP-C1206C224K3JAC7800_1206-MFG]  (hidden comment: C1206C224K3JAC7800)
C66  VDC_V: 16V  ValueDisplayed: 2.2uF  [FP-GRM155C81C225ME15D_0402-MFG]  (hidden comment: GRM155C81C225ME15D)
C67  VDC_V: 16V  ValueDisplayed: 2.2uF  [FP-GRM155C81C225ME15D_0402-MFG]  (hidden comment: GRM155C81C225ME15D)
C68  VDC_V: 16V  ValueDisplayed: 2.2uF  [FP-GRM155C81C225ME15D_0402-MFG]  (hidden comment: GRM155C81C225ME15D)
C69  VDC_V: 16V  ValueDisplayed: 2.2uF  [FP-GRM155C81C225ME15D_0402-MFG]  (hidden comment: GRM155C81C225ME15D)
C70  VDC_V: 16V  ValueDisplayed: 2.2uF  [FP-GRM155C81C225ME15D_0402-MFG]  (hidden comment: GRM155C81C225ME15D)
C71  VDC_V: 16V  ValueDisplayed: 2.2uF  [FP-GRM155C81C225ME15D_0402-MFG]  (hidden comment: GRM155C81C225ME15D)
C72  VDC_V: 16V  ValueDisplayed: 2.2uF  [FP-GRM155C81C225ME15D_0402-MFG]  (hidden comment: GRM155C81C225ME15D)
C73  VDC_V: 16V  ValueDisplayed: 2.2uF  [FP-GRM155C81C225ME15D_0402-MFG]  (hidden comment: GRM155C81C225ME15D)
C74  VDC_V: 16V  ValueDisplayed: 2.2uF  [FP-GRM155C81C225ME15D_0402-MFG]  (hidden comment: GRM155C81C225ME15D)
C75  VDC_V: 16V  ValueDisplayed: 2.2uF  [FP-GRM155C81C225ME15D_0402-MFG]  (hidden comment: GRM155C81C225ME15D)
C76  VDC_V: 16V  ValueDisplayed: 2.2uF  [FP-GRM155C81C225ME15D_0402-MFG]  (hidden comment: GRM155C81C225ME15D)
C77  VDC_V: 16V  ValueDisplayed: 2.2uF  [FP-GRM155C81C225ME15D_0402-MFG]  (hidden comment: GRM155C81C225ME15D)
C78  value 220nF  [FP-C1206C224K3JAC7800_1206-MFG]  (hidden comment: C1206C224K3JAC7800)
C79  value 220nF  [FP-C1206C224K3JAC7800_1206-MFG]  (hidden comment: C1206C224K3JAC7800)
C80  Cap_F: 1µF  VDC_V: 10V  [0201]  (hidden comment: GRM033R61A105ME15D)
C81  value 220nF  [FP-C1206C224K3JAC7800_1206-MFG]  (hidden comment: C1206C224K3JAC7800)
C82  value 220nF  [FP-C1206C224K3JAC7800_1206-MFG]  (hidden comment: C1206C224K3JAC7800)
C97  VDC_V: 50V  ValueDisplayed: 10pF  [0201_033]  (hidden comment: GRM0335C1H100JA01D)
C98  VDC_V: 50V  ValueDisplayed: 10pF  [0201_033]  (hidden comment: GRM0335C1H100JA01D)
C99  VDC_V: 50V  ValueDisplayed: 10pF  [0201_033]  (hidden comment: GRM0335C1H100JA01D)
C110  VDC_V: 50V  ValueDisplayed: 10pF  [0201_033]  (hidden comment: GRM0335C1H100JA01D)
C111  VDC_V: 50V  ValueDisplayed: 10pF  [0201_033]  (hidden comment: GRM0335C1H100JA01D)
C112  VDC_V: 50V  ValueDisplayed: 10pF  [0201_033]  (hidden comment: GRM0335C1H100JA01D)
C113  VDC_V: 50V  ValueDisplayed: 10pF  [0201_033]  (hidden comment: GRM0335C1H100JA01D)
C114  VDC_V: 50V  ValueDisplayed: 10pF  [0201_033]  (hidden comment: GRM0335C1H100JA01D)
C115  ValueDisplayed: 22µF  VDC_V: 25V  [0805_HV]  (hidden comment: GRT21BR61E226ME13L)
C116  ValueDisplayed: 22µF  VDC_V: 25V  [0805_HV]  (hidden comment: GRT21BR61E226ME13L)
C117  ValueDisplayed: 22µF  VDC_V: 25V  [0805_HV]  (hidden comment: GRT21BR61E226ME13L)
C118  ValueDisplayed: 22µF  VDC_V: 25V  [0805_HV]  (hidden comment: GRT21BR61E226ME13L)
C119  ValueDisplayed: 22µF  VDC_V: 25V  [0805_HV]  (hidden comment: GRT21BR61E226ME13L)
C120  ValueDisplayed: 22µF  VDC_V: 25V  [0805_HV]  (hidden comment: GRT21BR61E226ME13L)
C121  ValueDisplayed: 22µF  VDC_V: 25V  [0805_HV]  (hidden comment: GRT21BR61E226ME13L)
C122  ValueDisplayed: 22µF  VDC_V: 25V  [0805_HV]  (hidden comment: GRT21BR61E226ME13L)
C123  VDC_V: 100V  ValueDisplayed: 0.1uF  [0402]  (hidden comment: GRM155R62A104KE14D)
C124  VDC_V: 100V  ValueDisplayed: 0.1uF  [0402]  (hidden comment: GRM155R62A104KE14D)
C125  VDC_V: 100V  ValueDisplayed: 0.1uF  [0402]  (hidden comment: GRM155R62A104KE14D)
C126  VDC_V: 100V  ValueDisplayed: 0.1uF  [0402]  (hidden comment: GRM155R62A104KE14D)
C127  VDC_V: 100V  ValueDisplayed: 0.1uF  [0402]  (hidden comment: GRM155R62A104KE14D)
C128  VDC_V: 100V  ValueDisplayed: 0.1uF  [0402]  (hidden comment: GRM155R62A104KE14D)
C129  VDC_V: 50V  ValueDisplayed: 10pF  [0201_033]  (hidden comment: GRM0335C1H100JA01D)
C130  VDC_V: 50V  ValueDisplayed: 10pF  [0201_033]  (hidden comment: GRM0335C1H100JA01D)
C131  VDC_V: 50V  ValueDisplayed: 10pF  [0201_033]  (hidden comment: GRM0335C1H100JA01D)
C132  VDC_V: 50V  ValueDisplayed: 10pF  [0201_033]  (hidden comment: GRM0335C1H100JA01D)
C137  VDC_V: 100V  ValueDisplayed: 4.7uF  [FP-C2012X5R2A475K125AC_0805-MFG]  (hidden comment: C2012X5R2A475K125AC)
C138  VDC_V: 100V  ValueDisplayed: 4.7uF  [FP-C2012X5R2A475K125AC_0805-MFG]  (hidden comment: C2012X5R2A475K125AC)
Gnd1  3621-0-32-15-00-00-08-0  [Mill-Max_3621-0-32-xx-00-00-08-0]  (value not drawn)
Gnd2  3621-0-32-15-00-00-08-0  [Mill-Max_3621-0-32-xx-00-00-08-0]  (value not drawn)
Gnd3  3621-0-32-15-00-00-08-0  [Mill-Max_3621-0-32-xx-00-00-08-0]  (value not drawn)
Gnd4  3621-0-32-15-00-00-08-0  [Mill-Max_3621-0-32-xx-00-00-08-0]  (value not drawn)
Gnd5  3621-0-32-15-00-00-08-0  [Mill-Max_3621-0-32-xx-00-00-08-0]  (value not drawn)
Gnd6  3621-0-32-15-00-00-08-0  [Mill-Max_3621-0-32-xx-00-00-08-0]  (value not drawn)
J1  ASP-231707-01  [FP-FTSH-104-04-L-D-RA_HDR8-MFG]  (parts A,B of 2)
L1  BLM03AX241SN1D  [0201_033]  (value not drawn)
L2  BLM03AX241SN1D  [0201_033]  (value not drawn)
L3  BLM03AX241SN1D  [0201_033]  (value not drawn)
L4  BLM03AX241SN1D  [0201_033]  (value not drawn)
NT1  Net-Tie  [NetTie_0402]  (net tie, no BOM)
Q1  EPC2066  [D0650]
Q2  EPC2066  [D0650]
Q3  EPC2066  [D0650]
Q4  EPC2066  [D0650]
Q5  EPC2066  [D0650]
Q6  EPC2066  [D0650]
Q7  EPC2066  [D0650]
Q8  EPC2066  [D0650]
R1  RC0201JR-070RL  [FP-RC0201JR-070RL_0201 (0603 Metric)-IPC_C]  (value not drawn)
R2  ValueDisplayed: 10  [0201]  (hidden comment: RC0201JR-0710RL)
R3  ValueDisplayed: 2.00  [0201]  (hidden comment: RC0201FS-7D2RL)
R4  ValueDisplayed: 5.11k  [0201]  (hidden comment: RC0201DR-075K11L)
R5  ValueDisplayed: 2.00  [0201]  (hidden comment: RC0201FS-7D2RL)
R6  ValueDisplayed: 10  [0201]  (hidden comment: RC0201JR-0710RL)
R7  ValueDisplayed: 2.00  [0201]  (hidden comment: RC0201FS-7D2RL)
R8  ValueDisplayed: 5.11k  [0201]  (hidden comment: RC0201DR-075K11L)
R14  ValueDisplayed: 20.0  [0201_033]  (hidden comment: CRCW020120R0FNED)
R15  ValueDisplayed: 20.0  [0201_033]  (hidden comment: CRCW020120R0FNED)
R19  RC0201JR-070RL  [FP-RC0201JR-070RL_0201 (0603 Metric)-IPC_C]  (value not drawn)
R22  RC0201JR-070RL  [FP-RC0201JR-070RL_0201 (0603 Metric)-IPC_C]  (value not drawn)
R28  ValueDisplayed: 20.0  [0201_033]  (hidden comment: CRCW020120R0FNED)
R29  ValueDisplayed: 20.0  [0201_033]  (hidden comment: CRCW020120R0FNED)
R30  RC0201JR-070RL  [FP-RC0201JR-070RL_0201 (0603 Metric)-IPC_C]  (value not drawn)
R33  ValueDisplayed: 10  [0201]  (hidden comment: RC0201JR-0710RL)
R34  ValueDisplayed: 5.11k  [0201]  (hidden comment: RC0201DR-075K11L)
R35  ValueDisplayed: 10  [0201]  (hidden comment: RC0201JR-0710RL)
R36  ValueDisplayed: 5.11k  [0201]  (hidden comment: RC0201DR-075K11L)
R37  ValueDisplayed: 2.00  [0201]  (hidden comment: RC0201FS-7D2RL)
R38  RC0201JR-070RL  [FP-RC0201JR-070RL_0201 (0603 Metric)-IPC_C]  (value not drawn)
R39  RC0201JR-070RL  [FP-RC0201JR-070RL_0201 (0603 Metric)-IPC_C]  (value not drawn)
R40  ValueDisplayed: 2.00  [0201]  (hidden comment: RC0201FS-7D2RL)
R41  ValueDisplayed: 2.00  [0201]  (hidden comment: RC0201FS-7D2RL)
R42  ValueDisplayed: 2.00  [0201]  (hidden comment: RC0201FS-7D2RL)
R43  ValueDisplayed: 2.00  [0201]  (hidden comment: RC0201FS-7D2RL)
R44  RC0201JR-070RL  [FP-RC0201JR-070RL_0201 (0603 Metric)-IPC_C]  (value not drawn)
R45  RC0201JR-070RL  [FP-RC0201JR-070RL_0201 (0603 Metric)-IPC_C]  (value not drawn)
TP1  TESTPOINT  [TP_25MIL-SMT]  (value not drawn)  (no BOM)
TP2  TESTPOINT  [TP_25MIL-SMT]  (value not drawn)  (no BOM)
TP3  TESTPOINT  [TP_25MIL-SMT]  (value not drawn)  (no BOM)
TP4  TESTPOINT  [TP_25MIL-SMT]  (value not drawn)  (no BOM)
TP5  TESTPOINT  [TP_25MIL-SMT]  (value not drawn)  (no BOM)
TP6  TESTPOINT  [TP_25MIL-SMT]  (value not drawn)  (no BOM)
TP7  TESTPOINT  [TP_25MIL-SMT]  (value not drawn)  (no BOM)
TP8  TESTPOINT  [TP_25MIL-SMT]  (value not drawn)  (no BOM)
TP9  TESTPOINT  [TP_25MIL-SMT]  (value not drawn)  (no BOM)
TP12  TESTPOINT  [TP_25MIL-SMT]  (value not drawn)  (no BOM)
TP13  TESTPOINT  [TP_25MIL-SMT]  (value not drawn)  (no BOM)
TP14  TESTPOINT  [TP_25MIL-SMT]  (value not drawn)  (no BOM)
TP15  TESTPOINT  [TP_25MIL-SMT]  (value not drawn)  (no BOM)
U1  UCD7138DRS  [DRS0006A]
U2  LMG2100R044  [RAR0016A-MFG]
U3  UCD7138DRS  [DRS0006A]
U4  UCD7138DRS  [DRS0006A]
U5  LMG2100R044  [RAR0016A-MFG]
U6  UCD7138DRS  [DRS0006A]
Vin1  3621-0-32-15-00-00-08-0  [Mill-Max_3621-0-32-xx-00-00-08-0]  (value not drawn)
Vout1  3621-0-32-15-00-00-08-0  [Mill-Max_3621-0-32-xx-00-00-08-0]  (value not drawn)
Vout2  3621-0-32-15-00-00-08-0  [Mill-Max_3621-0-32-xx-00-00-08-0]  (value not drawn)
Vout3  3621-0-32-15-00-00-08-0  [Mill-Max_3621-0-32-xx-00-00-08-0]  (value not drawn)
Vout4  3621-0-32-15-00-00-08-0  [Mill-Max_3621-0-32-xx-00-00-08-0]  (value not drawn)
Vout5  3621-0-32-15-00-00-08-0  [Mill-Max_3621-0-32-xx-00-00-08-0]  (value not drawn)
Vout6  3621-0-32-15-00-00-08-0  [Mill-Max_3621-0-32-xx-00-00-08-0]  (value not drawn)

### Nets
AGND: NT1.2
GND: C1.1 C2.1 C3.1 C4.1 C5.1 C6.1 C7.1 C8.1 C9.1 C10.1 C11.2 C12.1 C14.1 C15.1 C16.1 C17.1 C18.1 C19.1 C20.1 C21.1 C22.1 C23.1 C24.1 C25.1 C26.1 C27.1 C28.1 C29.1 C30.1 C31.1 C32.1 C33.1 C34.1 C35.1 C36.1 C37.1 C38.2 C42.2 C48.1 C51.1 C52.1 C53.1 C54.1 C55.1 C56.1 C57.1 C58.1 C59.1 C60.1 C61.1 C62.1 C66.1 C67.1 C68.1 C69.1 C70.1 C71.1 C72.1 C73.1 C74.1 C75.1 C76.1 C77.1 C80.2 C97.1 C98.2 C99.1 C110.2 C111.1 C112.2 C113.1 C114.2 C115.2 C116.2 C117.2 C118.2 C119.2 C120.2 C121.2 C122.2 C123.2 C124.2 C125.2 C126.2 C127.2 C128.2 C129.1 C130.1 C131.1 C132.1 C137.1 C138.1 Gnd1.1 Gnd2.1 Gnd3.1 Gnd4.1 Gnd5.1 Gnd6.1 J1.4 NT1.1 Q1.2(S1) Q1.5(S2) Q1.6(S3) Q1.9(S4) Q1.10(S5) Q1.13(S6) Q1.14(S7) Q1.17(S8) Q1.18(S9) Q1.21(S10) Q1.22(S11) Q1.25(S12) Q1.26(S13) Q1.29(S14) Q1.30(Sub) Q2.2(S1) Q2.5(S2) Q2.6(S3) Q2.9(S4) Q2.10(S5) Q2.13(S6) Q2.14(S7) Q2.17(S8) Q2.18(S9) Q2.21(S10) Q2.22(S11) Q2.25(S12) Q2.26(S13) Q2.29(S14) Q2.30(Sub) Q3.2(S1) Q3.5(S2) Q3.6(S3) Q3.9(S4) Q3.10(S5) Q3.13(S6) Q3.14(S7) Q3.17(S8) Q3.18(S9) Q3.21(S10) Q3.22(S11) Q3.25(S12) Q3.26(S13) Q3.29(S14) Q3.30(Sub) Q4.2(S1) Q4.5(S2) Q4.6(S3) Q4.9(S4) Q4.10(S5) Q4.13(S6) Q4.14(S7) Q4.17(S8) Q4.18(S9) Q4.21(S10) Q4.22(S11) Q4.25(S12) Q4.26(S13) Q4.29(S14) Q4.30(Sub) Q5.2(S1) Q5.5(S2) Q5.6(S3) Q5.9(S4) Q5.10(S5) Q5.13(S6) Q5.14(S7) Q5.17(S8) Q5.18(S9) Q5.21(S10) Q5.22(S11) Q5.25(S12) Q5.26(S13) Q5.29(S14) Q5.30(Sub) Q6.2(S1) Q6.5(S2) Q6.6(S3) Q6.9(S4) Q6.10(S5) Q6.13(S6) Q6.14(S7) Q6.17(S8) Q6.18(S9) Q6.21(S10) Q6.22(S11) Q6.25(S12) Q6.26(S13) Q6.29(S14) Q6.30(Sub) Q7.2(S1) Q7.5(S2) Q7.6(S3) Q7.9(S4) Q7.10(S5) Q7.13(S6) Q7.14(S7) Q7.17(S8) Q7.18(S9) Q7.21(S10) Q7.22(S11) Q7.25(S12) Q7.26(S13) Q7.29(S14) Q7.30(Sub) Q8.2(S1) Q8.5(S2) Q8.6(S3) Q8.9(S4) Q8.10(S5) Q8.13(S6) Q8.14(S7) Q8.17(S8) Q8.18(S9) Q8.21(S10) Q8.22(S11) Q8.25(S12) Q8.26(S13) Q8.29(S14) Q8.30(Sub) R4.1 R8.1 R19.1 R22.1 R30.1 R34.1 R36.1 R45.1 TP12.1 TP13.1 TP14.1 TP15.1 U1.7(GND) U2.6(PGND) U2.15(AGND) U3.7(GND) U4.7(GND) U5.6(PGND) U5.15(AGND) U6.7(GND)
5V: C12.2 C48.2 J1.2 L1.1 L2.1 L3.1 L4.1 U2.14(VCC) U5.14(VCC)
DCT2A: R1.1 R44.1
DCT2B: R38.1 R39.1
JTAG_TCK: J1.6
JTAG_TDI: J1.3
JTAG_TDO: J1.8
JTAG_TMS: J1.1
PWM1A: U2.12(HI)
PWM1B: U2.13(LI)
PWM2A: R14.1 R29.1
PWM2B: R15.1 R28.1
PWM3A: U5.12(HI)
PWM3B: U5.13(LI)
SR1A2: R3.2 R5.1 U1.4(OUT)
SR1B2: R7.2 R37.1 U3.4(OUT)
SR2A2: R42.2 R43.1 U6.4(OUT)
SR2B2: R40.2 R41.1 U4.4(OUT)
Vin: C1.2 C2.2 C3.2 C4.2 C5.2 C6.2 C7.2 C8.2 C9.2 C10.2 C123.1 C124.1 C125.1 C126.1 C127.1 C128.1 C137.2 C138.2 U2.7(VIN) U5.7(VIN) Vin1.1
Vout: C14.2 C15.2 C16.2 C17.2 C18.2 C19.2 C20.2 C21.2 C22.2 C23.2 C24.2 C25.2 C26.2 C27.2 C28.2 C29.2 C30.2 C31.2 C32.2 C33.2 C34.2 C35.2 C36.2 C37.2 C51.2 C52.2 C53.2 C54.2 C55.2 C56.2 C57.2 C58.2 C59.2 C60.2 C61.2 C62.2 C66.2 C67.2 C68.2 C69.2 C70.2 C71.2 C72.2 C73.2 C74.2 C75.2 C76.2 C77.2 C115.1 C116.1 C117.1 C118.1 C119.1 C120.1 C121.1 C122.1 Q1.3(D1) Q1.4(D2) Q1.7(D3) Q1.8(D4) Q1.11(D5) Q1.12(D6) Q1.15(D7) Q1.16(D8) Q1.19(D9) Q1.20(D10) Q1.23(D11) Q1.24(D12) Q1.27(D13) Q1.28(D14) Q2.3(D1) Q2.4(D2) Q2.7(D3) Q2.8(D4) Q2.11(D5) Q2.12(D6) Q2.15(D7) Q2.16(D8) Q2.19(D9) Q2.20(D10) Q2.23(D11) Q2.24(D12) Q2.27(D13) Q2.28(D14) Q3.3(D1) Q3.4(D2) Q3.7(D3) Q3.8(D4) Q3.11(D5) Q3.12(D6) Q3.15(D7) Q3.16(D8) Q3.19(D9) Q3.20(D10) Q3.23(D11) Q3.24(D12) Q3.27(D13) Q3.28(D14) Q4.3(D1) Q4.4(D2) Q4.7(D3) Q4.8(D4) Q4.11(D5) Q4.12(D6) Q4.15(D7) Q4.16(D8) Q4.19(D9) Q4.20(D10) Q4.23(D11) Q4.24(D12) Q4.27(D13) Q4.28(D14) Q5.3(D1) Q5.4(D2) Q5.7(D3) Q5.8(D4) Q5.11(D5) Q5.12(D6) Q5.15(D7) Q5.16(D8) Q5.19(D9) Q5.20(D10) Q5.23(D11) Q5.24(D12) Q5.27(D13) Q5.28(D14) Q6.3(D1) Q6.4(D2) Q6.7(D3) Q6.8(D4) Q6.11(D5) Q6.12(D6) Q6.15(D7) Q6.16(D8) Q6.19(D9) Q6.20(D10) Q6.23(D11) Q6.24(D12) Q6.27(D13) Q6.28(D14) Q7.3(D1) Q7.4(D2) Q7.7(D3) Q7.8(D4) Q7.11(D5) Q7.12(D6) Q7.15(D7) Q7.16(D8) Q7.19(D9) Q7.20(D10) Q7.23(D11) Q7.24(D12) Q7.27(D13) Q7.28(D14) Q8.3(D1) Q8.4(D2) Q8.7(D3) Q8.8(D4) Q8.11(D5) Q8.12(D6) Q8.15(D7) Q8.16(D8) Q8.19(D9) Q8.20(D10) Q8.23(D11) Q8.24(D12) Q8.27(D13) Q8.28(D14) R2.2 R6.2 R33.2 R35.2 TP1.1 TP2.1 TP3.1 TP4.1 TP5.1 TP6.1 Vout1.1 Vout2.1 Vout3.1 Vout4.1 Vout5.1 Vout6.1
Vsw1: C39.2 C40.2 C41.2 C43.2 C44.2 C45.2 C46.2 C47.2 C49.2 C63.2 C64.2 C65.2 C78.2 C79.2 C81.2 C82.2 TP7.1 TP9.1 U2.5(SW)
Vsw2: C39.1 C40.1 C41.1 C43.1 C44.1 C45.1 C46.1 C47.1 C49.1 C63.1 C64.1 C65.1 C78.1 C79.1 C81.1 C82.1 TP8.1 U5.5(SW)
NetC11_1: C11.1 L1.2 U1.3(VCC)
NetC13_1: C13.1 U2.10(HB)
NetC13_2: C13.2 U2.11(HS)
NetC38_1: C38.1 L2.2 U3.3(VCC)
NetC42_1: C42.1 L3.2 U4.3(VCC)
NetC50_1: C50.1 U5.10(HB)
NetC50_2: C50.2 U5.11(HS)
NetC80_1: C80.1 L4.2 U6.3(VCC)
NetC97_2: C97.2 Q1.1(G) R3.1
NetC98_1: C98.1 Q2.1(G) R5.2
NetC99_2: C99.2 Q3.1(G) R7.1
NetC110_1: C110.1 Q4.1(G) R37.2
NetC111_2: C111.2 Q5.1(G) R40.1
NetC112_1: C112.1 Q6.1(G) R41.2
NetC113_2: C113.2 Q7.1(G) R42.1
NetC114_1: C114.1 Q8.1(G) R43.2
NetC129_2: C129.2 R14.2 U1.1(IN)
NetC130_2: C130.2 R15.2 U3.1(IN)
NetC131_2: C131.2 R28.2 U4.1(IN)
NetC132_2: C132.2 R29.2 U6.1(IN)
NetR1_2: R1.2 U1.2(DCT)
NetR2_1: R2.1 R4.2 U1.5(VD)
NetR6_1: R6.1 R8.2 U3.5(VD)
NetR19_2: R19.2 U3.6(CTRL)
NetR22_2: R22.2 U1.6(CTRL)
NetR30_2: R30.2 U4.6(CTRL)
NetR33_1: R33.1 R34.2 U4.5(VD)
NetR35_1: R35.1 R36.2 U6.5(VD)
NetR38_2: R38.2 U3.2(DCT)
NetR39_2: R39.2 U4.2(DCT)
NetR44_2: R44.2 U6.2(DCT)
NetR45_2: R45.2 U6.6(CTRL)

Not connected (* = marked no-connect by the designer): J1 5 7; U2 1(NC)* 2(NC)* 3(NC)* 4(NC)* 8(NC)* 9(NC)* 16(NC)*; U5 1(NC)* 2(NC)* 3(NC)* 4(NC)* 8(NC)* 9(NC)* 16(NC)*

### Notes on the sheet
- Rev
- N/A
- ECN #
- Approved Date
- Approved by
- Revision History
- Notes
- 4 parallel turns
- 2 series turns
- 2 parallel turns
- (near TP9) 2 series turns
- (near TP9) 2 parallel turns
- (near Vout6) Female connector: 0312-0-15-15-34-27-10-0

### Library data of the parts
C1-C10 C137 C138 = CMP-0098058-1: 4.7 µF ±10% 100V Ceramic Capacitor X5R 0805 (2012 Metric); Manufacturer: TDK; TempCo: 15%; Value: 4.7µF; SizeZ_mm: 1.5mm; AEC Qualified: No
C11 C38 C42 C80 = CMP-0064909-1: CAP, CERM, 1 uF, 10 V,+/- 20%, X5R, 0201; Manufacturer: MuRata; TaMin_C: -55°C; Polarized: N; SizeAreaWB_mm2: 2.08; Value1: Unknown; U/M: EA; Value: 1uF; TaMax_C: 85°C; SizeZ_mm: 0.26; SizeX_mm: 0.6; SizeY_mm: 0.3; SizeArea_mm2: 0.18; AEC Category: Q200
C12 C13 C48 C50 = CMP-0006204-2: CAP, CERM, 0.1 uF, 16 V, +/- 10%, X5R, 0402; Manufacturer: Johanson Technology; TaMin_C: -55°C; Polarized: N; SizeAreaWB_mm2: 3; Value1: Unknown; U/M: EA; Value: 0.1uF; TaMax_C: 85°C; SizeZ_mm: 0.65; SizeX_mm: 1; SizeY_mm: 0.5; Cap_Case: 0402; Cap_F: 100nF; AEC Category: Q200
C14-C37 C51-C62 C66-C77 = CMP-0001414-1: Chip Multilayer Ceramic Capacitors for General Purpose, 0402, 2.2uF, X6S, 22%, 20%, 16V; Manufacturer: Murata; Value: 2.2µF; SizeZ_mm: 0.55mm; AEC Qualified: No
C39-C41 C43-C47 C49 C63-C65 C78 C79 C81 C82 = CMP-0001410-1: 0.22 µF ±10% 25V Ceramic Capacitor U2J 1206 (3216 Metric); Manufacturer: KEMET; TempCo: -750+/-120ppm/°C; SizeZ_mm: 1.8mm; AEC Qualified: No; ValueDisplayed: 0.22uF
C97-C99 C110-C114 C129-C132 = CMP-0086057-1: as C86 on sheet PMP23340E3_C2K_Control
C115-C122 = CMP-0084680-1: CAP, CERM, 22 µF, 25 V,+/- 20%, X5R, AEC-Q200 Grade 3, 0805; Manufacturer: MuRata; SizeX_mm: 2; SizeAreaWB_mm2: 6.75; Cap_Case: 0805; AEC Grade: 3; SizeY_mm: 1.25; SizeArea_mm2: 2.5; SizeZ_mm: 1.45; U/M: EA; Polarized: N; AEC Category: Q200; Value: 22uF; TaMin_C: -55°C; AEC Qualified: Y; TaMax_C: 85°C
C123-C128 = CMP-0006618-2: CAP, CERM, 0.1 uF, 100 V, +/- 10%, X5R, 0402; Manufacturer: MuRata; TaMin_C: -55°C; Polarized: N; SizeAreaWB_mm2: 3; Value1: Unknown; U/M: EA; Value: 0.1uF; TaMax_C: 85°C; SizeZ_mm: 0.6; SizeX_mm: 1; SizeY_mm: 0.5; Cap_F: 100nF; AEC Category: Q200
Gnd1-Gnd6 Vin1 Vout1-Vout6 = CMP-0082316-1: PCB Pin, 0.04" DIA, Edge-Mount; Manufacturer: Mill-Max; CompType: PCB Pin; ContactFinish: Gold; Gender: Male; Row_Count: 1
J1 = CMP-0003661-1: Like part: FTSH-104-04-L-D-RA; Manufacturer: Samtec; ContactFinish: Gold,Nickel; Current_A: 3.4A; Row_Count: 2; AEC Qualified: No; Conn Gender: Male; Conn Orientation: Right Angle; DUT-Pitch_mm: 1.27mm; SizeZ_mm: 3.56mm; TaMax_C: +125°C; TaMin_C: -55°C
L1-L4 = CMP-0084501-1: Inductor, Ferrite Bead, Ferrite, 0.35 A, 0.38 ohm, SMD; Manufacturer: MuRata; SizeX_mm: 0.6; SizeY_mm: 0.3; Imax_A: 350mA; AEC Category: Q200; SizeArea_mm2: 0.18; SizeZ_mm: 0.33; SizeAreaWB_mm2: 2.08; Value2: 0.35A; AEC Qualified: N; DCR_ohm: 0.38
NT1 = CMP-0078142-6: Single point connection between nets.
Q1-Q8 = EPC2066: 40V 1.1mE 90A; MFG: EPC; Name: Aspen
R1 R19 R22 R30 R38 R39 R44 R45 = CMP-0086442-2: RES SMD 0 OHM JUMPER 1/20W 0201; Manufacturer: Yageo; Power_W: 50mW; VDC_V: 25V; AEC Qualified: No; Res_ohm: 0; Tolerance_%: 5%; TempCo: 200ppm/°C; SizeZ_mm: 0.26mm
R2 R6 R33 R35 = CMP-0027021-3: RES, 10, 5%, 0.05 W, 0201; Manufacturer: Yageo America; Power_W: 50mW; TempCo: 350 ppm/C; Value_Code: 10R0; U/M: EA; Value: 10; EIA_Code: E24; SizeX_mm: 0.6; SizeY_mm: 0.3; SizeZ_mm: 0.26; Value2: 0.05W; SizeArea_mm2: 0.18; AEC Qualified: N; VDC_V: 25V; AEC Category: Q200
R3 R5 R7 R37 R40-R43 = CMP-0028098-1: RES, 2.00, 1%, 0.05 W, 0201; Manufacturer: Yageo America; Power_W: 50mW; TempCo: 350 ppm/C; Value_Code: 2R00; U/M: EA; Value: 2.00; EIA_Code: E96; Res_ohm: 2; SizeX_mm: 0.6; SizeY_mm: 0.3; SizeZ_mm: 0.26; Value2: 0.05W; SizeArea_mm2: 0.18; AEC Qualified: N; VDC_V: 25V; AEC Category: Q200
R4 R8 R34 R36 = CMP-0028226-1: RES, 5.11 k, 0.5%, 0.05 W, 0201; Manufacturer: Yageo America; Power_W: 50mW; TempCo: 200 ppm/C; Value_Code: 5k11; U/M: EA; Value: 5.11k; EIA_Code: E192; SizeX_mm: 0.6; SizeY_mm: 0.3; SizeZ_mm: 0.26; Value2: 0.05W; SizeArea_mm2: 0.18; AEC Qualified: N; VDC_V: 25V; AEC Category: Q200
R14 R15 R28 R29 = CMP-0078192-2: RES, 20.0, 1%, 0.05 W, 0201; Manufacturer: Vishay-Dale; Value_Code: 20R0; SizeArea_mm2: 0.18; AEC Qualified: N; AEC Category: Q200; Res_ohm: 20; Value: 20.0; SizeZ_mm: 0.33; EIA_Code: E96; TempCo: 200 ppm/C; Power_W: 50mW; VDC_V: 30V; SizeY_mm: 0.3; Value2: 0.05W; SizeX_mm: 0.6
TP1-TP9 TP12-TP15 = CMP-0078143-3: TEST POINT.  No entry in BOM.
U1 U3 U4 U6 = CMP-0013422-3: UCD7xxx Low Side Power MOSFET Driver with Body Diode Conduction Sensing, DRS0006A (WSON-6); Manufacturer: Texas Instruments; SizeZ_mm: 0.8; SizeX_mm: 3; SizeArea_mm2: 9; CompType: IC; U/M: EA; SizeAreaWB_mm2: 16
U2 U5 = CMP-0097820-2: Manufacturer: Texas Instruments; AEC Category: Q200; CompType: IC; Standoff Height: 0mm; SizeZ_mm: 0.89mm

## Sheet PMP23340E3_C2K_Hardware.SchDoc
size 431 x 279 mm; Date: Not shown in title block; ApprovedBy: Not shown in title block; CheckedBy: Not shown in title block; Author: Not shown in title block; CompanyName: Not shown in title block; Engineer: Not shown in title block; Organization: Not shown in title block; Address1: Not shown in title block; Address2: Not shown in title block; Address3: Not shown in title block; Address4: Not shown in title block; DocumentNumber: 3; Revision: Use project parameter SCH_Rev; SheetNumber: 3; SheetTotal: 3; PageSetup: Record=PageOptions¦CenterHorizontal=True¦CenterVertical=True¦PrintScale=1.00¦XCorrection=1.00¦YCorrection=1.00¦PrintKind=0¦BorderSize=5000000¦LeftOffset=0¦BottomOffset=0¦Orientation=2¦PaperLength=1000¦PaperWidth=1000¦Scale=100¦PaperSource=15¦PrintQuality=600¦MediaType=1¦DitherType=10¦PaperKind=Letter¦PrintScaleMode=1
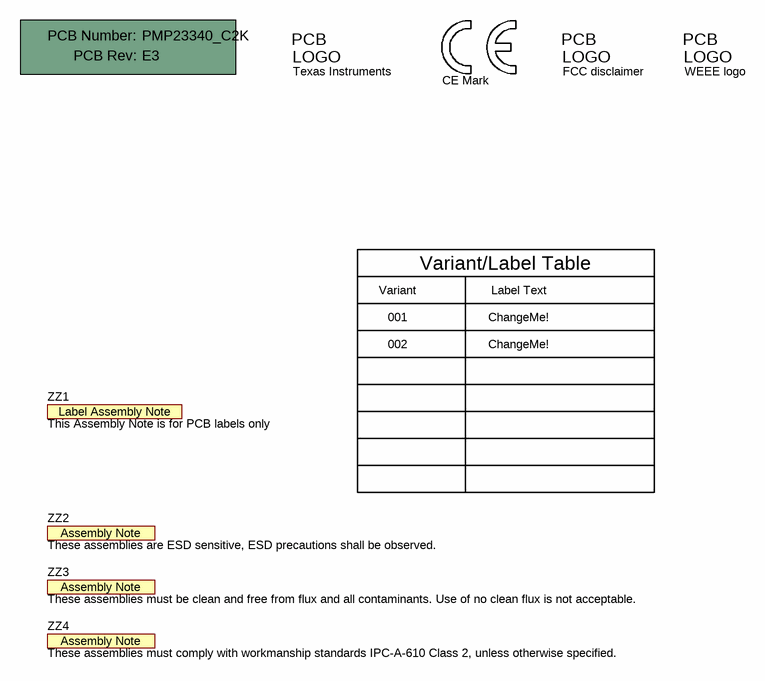
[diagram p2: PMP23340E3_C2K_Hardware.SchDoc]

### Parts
!PCB1  Printed Circuit Board  (value not drawn)  (mechanical)
Logo1  CE Mark  [CE_Mark_5mm]  (no BOM)
Logo2  Texas Instruments  [TI_Symbol_Overlay_Small]  (no BOM)
Logo3  FCC disclaimer  [FCC_disclaimer]  (no BOM)
Logo4  WEEE logo  [WEEE_Minimum]  (no BOM)
ZZ1  This Assembly Note is for PCB labels only  [AssemblyNoteLabel]  (no BOM)
ZZ2  These assemblies are ESD sensitive, ESD precautions shall be observed.  [AssemblyNote]  (no BOM)
ZZ3  These assemblies must be clean and free from flux and all contaminants. Use of no clean flux is not acceptable.  [AssemblyNote]  (no BOM)
ZZ4  These assemblies must comply with workmanship standards IPC-A-610 Class 2, unless otherwise specified.  [AssemblyNote]  (no BOM)

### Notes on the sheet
- Variant
- Variant/Label Table
- Label Text
- 001
- 002
- ChangeMe!

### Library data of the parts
!PCB1 = CMP-0003618-2: Manufacturer: Any; PartNumber: PMP23340_C2K
Logo1 = CMP-0074844-1: SymbolCreator: a0412235
Logo2 = CMP-0074838-1: Texas Instrument Corporate Signature; SymbolCreator: a0412235; Lib Reference: TI_Logo; Library Reference: Logo
Logo3 = CMP-0074847-1: FCC_disclaimer; Library Reference: Logo
Logo4 = CMP-0074769-1
ZZ1 = CMP-0003616-3
ZZ2 = CMP-0077236-1
ZZ3 = CMP-0077237-1
ZZ4 = CMP-0077238-1

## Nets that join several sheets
AGND: PMP23340E3_C2K_Control (38 pins), PMP23340E3_C2K_Power_Stage (NT1.2)
5V: PMP23340E3_C2K_Control (C83.1 U8.4 U8.6), PMP23340E3_C2K_Power_Stage (9 pins)
DCT2A: PMP23340E3_C2K_Control (C91.1 U7.31), PMP23340E3_C2K_Power_Stage (R1.1 R44.1)
DCT2B: PMP23340E3_C2K_Control (C90.1 U7.21), PMP23340E3_C2K_Power_Stage (R38.1 R39.1)
JTAG_TCK: PMP23340E3_C2K_Control (U7.16), PMP23340E3_C2K_Power_Stage (J1.6)
JTAG_TDI: PMP23340E3_C2K_Control (U7.19), PMP23340E3_C2K_Power_Stage (J1.3)
JTAG_TDO: PMP23340E3_C2K_Control (U7.17), PMP23340E3_C2K_Power_Stage (J1.8)
JTAG_TMS: PMP23340E3_C2K_Control (R10.1 U7.18), PMP23340E3_C2K_Power_Stage (J1.1)
PWM1A: PMP23340E3_C2K_Control (C92.1 U7.28), PMP23340E3_C2K_Power_Stage (U2.12)
PWM1B: PMP23340E3_C2K_Control (C93.1 U7.27), PMP23340E3_C2K_Power_Stage (U2.13)
PWM2A: PMP23340E3_C2K_Control (C95.1 U7.29), PMP23340E3_C2K_Power_Stage (R14.1 R29.1)
PWM2B: PMP23340E3_C2K_Control (C94.1 U7.26), PMP23340E3_C2K_Power_Stage (R15.1 R28.1)
PWM3A: PMP23340E3_C2K_Control (C87.1 U7.13), PMP23340E3_C2K_Power_Stage (U5.12)
PWM3B: PMP23340E3_C2K_Control (C86.1 U7.30), PMP23340E3_C2K_Power_Stage (U5.13)
Vin: PMP23340E3_C2K_Control (R21.2), PMP23340E3_C2K_Power_Stage (21 pins)
Vout: PMP23340E3_C2K_Control (R20.2), PMP23340E3_C2K_Power_Stage (184 pins)
Vsw1: PMP23340E3_C2K_Control (R25.1), PMP23340E3_C2K_Power_Stage (19 pins)
Vsw2: PMP23340E3_C2K_Control (R17.1), PMP23340E3_C2K_Power_Stage (18 pins)

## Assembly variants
001: not fitted C97 C98 C99 C110 C111 C112 C113 C114 R4 R8 R34 R36 R39 R44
